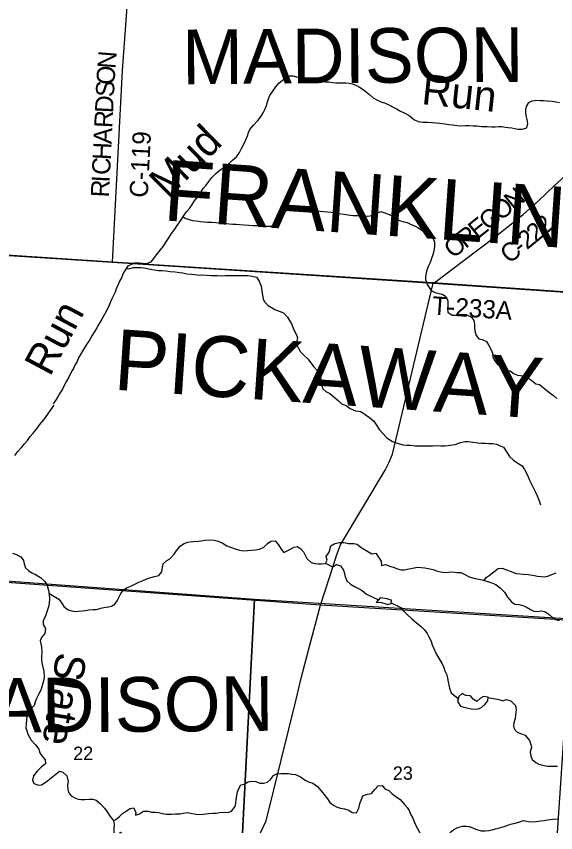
# Model space of a CAD drawing. Extents: x 114843 to 284848, y 317643 to 566895.
# Drawn here: x 240725 to 249598, y 317643 to 331087 of the extents above; entities that cross this region are included whole.
import ezdxf

# ---------------------------------------------------------------- set-up
doc = ezdxf.new("R2010")
doc.units = 0
for name, color, linetype in [('GM_X_County', 7, 'Continuous'), ('GM_X_County_Road', 7, 'Continuous'), ('GM_X_County_Road_Text', 7, 'Continuous'), ('GM_X_County_Text', 7, 'Continuous'), ('GM_X_Minor_Lake', 7, 'Continuous'), ('GM_X_Minor_River', 7, 'Continuous'), ('GM_X_Minor_River_Text', 7, 'Continuous'), ('GM_X_Section', 7, 'Continuous'), ('GM_X_Section_Text', 7, 'Continuous'), ('GM_X_Township', 7, 'Continuous'), ('GM_X_Township_Road', 7, 'Continuous'), ('GM_X_Township_Road_Text', 7, 'Continuous'), ('GM_X_Township_Text', 7, 'Continuous')]:
    doc.layers.add(name, color=color, linetype=linetype)

msp = doc.modelspace()

# ---------------------------------------------------------------- linework, layer by layer
at = {"layer": 'GM_X_County'}
for points in [[(256093, 333696), (255814, 329636), (255762, 328822), (255618, 326883), (255575, 326129), (250997, 326464), (247583, 326697), (242307, 327039), (239655, 327214), (237015, 327375), (235162, 327503), (234342, 327551), (226718, 328004)], [(226718, 328004), (234342, 327551), (235162, 327503), (237015, 327375), (239655, 327214), (242307, 327039), (247583, 326697), (250997, 326464), (255575, 326129), (255217, 320838), (255033, 318174), (254997, 317643)]]:
    msp.add_lwpolyline(points, dxfattribs=at)
at = {"layer": 'GM_X_County_Road'}
msp.add_line((242308, 327036), (247584, 326695), dxfattribs=at)
for points in [[(242308, 327036), (242471, 330193), (242573, 331623), (242715, 333489)], [(247584, 326695), (247638, 326724), (248073, 327052), (248608, 327461), (249062, 327824), (249315, 328047), (249579, 328303), (249934, 328627), (250418, 329010), (250414, 329113), (250426, 329371), (250481, 330134), (250500, 330420)], [(237016, 327373), (239656, 327212), (239661, 327211), (242308, 327036)], [(244744, 317643), (244836, 317836), (245331, 319839), (245413, 320188), (245534, 320650), (245663, 321145), (245728, 321388), (245946, 322063), (245997, 322223), (246060, 322382), (246793, 323614), (246855, 323734), (246912, 323877), (247584, 326695)]]:
    msp.add_lwpolyline(points, dxfattribs=at)
at = {"layer": 'GM_X_Minor_Lake'}
for points in [[(246824, 321492), (246713, 321513), (246645, 321434)], [(246645, 321434), (246713, 321437), (246771, 321421), (246839, 321399), (246891, 321419), (246899, 321471), (246837, 321489), (246824, 321492)], [(248005, 319888), (247984, 319806), (248032, 319724), (248086, 319712), (248156, 319696), (248210, 319680), (248274, 319676), (248330, 319684), (248385, 319709), (248439, 319757), (248481, 319817), (248485, 319873), (248413, 319887), (248363, 319859), (248299, 319801), (248243, 319840), (248197, 319896), (248123, 319902), (248108, 319910)], [(248108, 319910), (248059, 319934), (248005, 319888)]]:
    msp.add_lwpolyline(points, dxfattribs=at)
at = {"layer": 'GM_X_Minor_River'}
for points in [[(242556, 326975), (242671, 327029), (242749, 327028), (242803, 327022), (242869, 327014), (242941, 327045), (242986, 327099), (243048, 327179), (243096, 327242), (243145, 327302), (243189, 327372), (243232, 327439), (243278, 327511), (243330, 327581), (243373, 327644), (243415, 327700), (243447, 327752), (243483, 327804), (243532, 327871), (243574, 327923), (243614, 327977), (243653, 328040), (243711, 328116), (243749, 328168), (243800, 328251), (243848, 328307), (243890, 328369), (243943, 328434), (244009, 328500), (244079, 328556), (244158, 328615), (244230, 328671), (244282, 328716), (244347, 328774), (244397, 328846), (244431, 328911), (244466, 328981), (244500, 329053), (244528, 329119), (244547, 329172), (244569, 329222), (244629, 329296), (244698, 329369), (244754, 329445), (244786, 329497), (244811, 329552), (244839, 329618), (244855, 329680), (244872, 329730), (244896, 329784), (244942, 329853), (244993, 329927), (245049, 329991), (245099, 330032), (245172, 330084), (245222, 330106), (245276, 330105), (245332, 330091), (245386, 330075), (245448, 330054), (245500, 330034), (245560, 330022), (245616, 330014), (245680, 330015), (245746, 330011), (245806, 330007), (245866, 330006), (245928, 329998), (245982, 329994), (246036, 329993), (246092, 329991), (246144, 329989), (246198, 329986), (246258, 329974), (246320, 329948), (246372, 329922), (246430, 329881), (246482, 329843), (246535, 329797), (246593, 329747), (246657, 329712), (246721, 329680), (246781, 329662), (246851, 329629), (246923, 329593), (246979, 329563), (247045, 329525), (247107, 329498), (247186, 329454), (247262, 329390), (247334, 329355), (247412, 329343), (247490, 329344), (247572, 329338), (247634, 329334), (247692, 329327), (247772, 329317), (247840, 329307), (247898, 329302), (247976, 329290)], [(247976, 329290), (248040, 329285), (248113, 329287), (248169, 329287), (248239, 329284), (248303, 329282), (248379, 329274), (248473, 329271), (248549, 329267), (248605, 329268), (248661, 329272), (248713, 329270), (248767, 329264), (248819, 329257), (248875, 329249), (248927, 329239), (248983, 329230), (249049, 329226), (249121, 329248), (249140, 329322), (249130, 329389), (249114, 329452), (249108, 329503), (249107, 329553), (249117, 329603), (249159, 329665), (249209, 329695), (249284, 329704), (249344, 329702), (249400, 329698), (249458, 329693), (249538, 329691), (249662, 329668)], [(243471, 327787), (243511, 327758), (243569, 327739), (243621, 327727), (243685, 327717), (243755, 327708), (243815, 327700), (243871, 327698), (243943, 327695), (244009, 327689), (244069, 327685), (244147, 327680), (244224, 327672), (244286, 327666), (244342, 327663), (244398, 327659), (244474, 327655), (244550, 327648), (244614, 327644), (244682, 327641), (244738, 327637), (244794, 327631), (244860, 327629), (244912, 327632), (244982, 327660), (245038, 327723), (245079, 327781), (245121, 327833), (245167, 327889), (245228, 327914), (245306, 327922), (245382, 327913), (245438, 327907), (245492, 327899), (245568, 327894), (245666, 327884), (245726, 327878), (245784, 327875), (245844, 327867), (245902, 327861), (245980, 327854), (246038, 327840), (246118, 327826), (246178, 327817), (246264, 327807), (246336, 327804), (246388, 327806), (246440, 327802), (246510, 327795), (246580, 327805), (246653, 327847), (246721, 327874), (246773, 327858), (246859, 327822), (246913, 327795), (246968, 327757), (247026, 327727), (247100, 327702), (247154, 327690), (247212, 327666), (247278, 327638), (247330, 327611), (247400, 327561), (247452, 327511), (247518, 327482), (247585, 327430), (247605, 327370), (247605, 327294), (247596, 327218), (247578, 327158), (247554, 327099), (247532, 327031), (247505, 326979), (247479, 326909), (247469, 326859), (247454, 326802), (247458, 326752), (247486, 326671)], [(242558, 326976), (242518, 326909), (242484, 326855), (242459, 326791), (242421, 326723), (242399, 326670), (242369, 326598), (242349, 326546), (242326, 326488), (242296, 326436), (242276, 326384), (242252, 326329), (242200, 326225), (242161, 326151), (242131, 326099), (242083, 326017), (242049, 325956), (242017, 325900), (241966, 325824), (241930, 325756), (241888, 325699), (241850, 325637), (241817, 325585), (241779, 325519), (241747, 325465), (241727, 325401), (241689, 325344), (241664, 325288), (241634, 325236), (241586, 325146), (241550, 325080), (241514, 325009), (241485, 324945), (241443, 324883), (241407, 324819), (241371, 324761), (241333, 324704)], [(242533, 326932), (242574, 326929), (242646, 326950), (242700, 326952), (242780, 326950), (242854, 326938), (242932, 326924), (242994, 326912), (243062, 326903), (243119, 326899), (243183, 326893), (243253, 326883), (243339, 326879), (243409, 326870), (243463, 326862), (243529, 326848), (243607, 326838), (243667, 326834), (243725, 326824), (243795, 326829), (243857, 326825), (243927, 326821), (243979, 326819), (244036, 326819), (244096, 326815), (244162, 326818), (244242, 326818), (244306, 326820), (244376, 326818), (244430, 326820), (244482, 326820), (244534, 326817), (244606, 326805), (244678, 326791), (244722, 326725), (244754, 326645), (244766, 326565), (244774, 326495), (244787, 326435), (244807, 326383), (244867, 326325), (244979, 326257), (245051, 326229), (245119, 326203), (245185, 326135), (245219, 326077), (245255, 326009), (245287, 325937), (245319, 325873), (245349, 325795), (245332, 325723), (245340, 325673), (245366, 325621), (245402, 325559), (245452, 325509), (245524, 325443), (245564, 325387), (245618, 325317), (245678, 325251), (245707, 325197), (245737, 325115), (245751, 325061), (245751, 325003), (245765, 324951), (245819, 324907), (245883, 324873), (245951, 324821), (246019, 324762), (246077, 324706), (246151, 324678), (246219, 324626), (246305, 324592), (246393, 324580), (246463, 324532), (246537, 324481), (246605, 324421), (246648, 324353), (246698, 324277), (246764, 324205), (246820, 324147), (246916, 324087), (246994, 324055), (247084, 324029), (247148, 324022), (247204, 324022), (247284, 324016), (247338, 324014), (247395, 324012), (247467, 324012), (247521, 324015), (247579, 324015), (247647, 324017), (247709, 324013), (247771, 324015), (247829, 324021), (247893, 324028), (247945, 324034), (248030, 324068), (248108, 324084), (248160, 324085), (248236, 324075)], [(247486, 326671), (247547, 326571), (247615, 326541), (247681, 326523), (247736, 326513), (247793, 326471), (247825, 326403), (247825, 326325), (247817, 326273), (247825, 326215), (247895, 326167), (247949, 326167), (248003, 326175), (248057, 326177), (248123, 326176), (248213, 326134), (248253, 326078), (248265, 326018), (248265, 325958), (248267, 325908), (248290, 325830), (248336, 325776), (248390, 325764), (248460, 325732), (248500, 325668), (248538, 325596), (248558, 325538), (248566, 325480), (248594, 325418), (248636, 325364), (248718, 325296), (248774, 325264), (248848, 325246), (248914, 325202), (248968, 325178), (249020, 325171), (249072, 325169), (249142, 325133), (249206, 325091), (249272, 325035), (249334, 325021), (249422, 324953), (249508, 324879), (249560, 324844), (249617, 324794)], [(240701, 323853), (240748, 323919), (240812, 323984), (240860, 324044), (240909, 324100), (240953, 324167), (241003, 324221), (241056, 324289), (241104, 324359), (241175, 324444), (241347, 324683)], [(248236, 324075), (248316, 324065), (248378, 324059), (248442, 324055), (248498, 324053), (248564, 324052), (248626, 324042), (248686, 324016), (248738, 323992), (248790, 323916), (248840, 323840), (248902, 323776), (248978, 323728), (249046, 323684), (249086, 323622), (249122, 323554), (249145, 323504), (249169, 323450), (249219, 323352), (249265, 323250), (249291, 323188), (249321, 323124), (249349, 323042)], [(241260, 321589), (241422, 321490), (241462, 321440), (241508, 321368), (241578, 321314), (241638, 321294), (241692, 321288), (241744, 321290), (241808, 321295), (241862, 321303), (241918, 321313), (241987, 321317), (242041, 321317), (242113, 321338), (242167, 321354), (242239, 321360), (242291, 321376), (242345, 321408), (242383, 321460), (242412, 321515), (242440, 321571), (242484, 321639), (242536, 321677), (242596, 321699), (242666, 321730), (242739, 321770), (242823, 321800), (242899, 321832), (242999, 321863), (243071, 321879), (243118, 321939), (243130, 322013), (243138, 322073), (243200, 322124), (243250, 322152), (243319, 322228), (243365, 322294), (243423, 322369), (243485, 322403), (243549, 322425), (243630, 322437), (243714, 322446), (243766, 322450), (243828, 322462), (243896, 322468), (243978, 322458), (244048, 322443), (244110, 322415), (244188, 322367), (244262, 322337), (244324, 322315), (244398, 322297), (244458, 322287), (244530, 322290), (244594, 322294), (244659, 322302), (244727, 322314), (244795, 322343), (244859, 322407), (244911, 322443), (244983, 322449), (245037, 322381), (245083, 322311), (245127, 322255), (245179, 322283), (245293, 322346), (245344, 322358), (245408, 322320), (245448, 322268), (245505, 322156), (245575, 322094), (245635, 322076), (245691, 322069), (245743, 322071), (245809, 322077), (245840, 322131), (245824, 322191), (245870, 322261), (245900, 322366), (245965, 322408), (246043, 322424), (246115, 322422), (246189, 322406), (246279, 322407), (246331, 322395), (246397, 322341), (246451, 322309), (246517, 322267), (246571, 322233), (246641, 322246), (246681, 322180), (246727, 322112), (246735, 322043), (246799, 322058), (246871, 322032), (246943, 322012), (246995, 321986), (247055, 321972), (247107, 321972), (247181, 321987), (247245, 321999)], [(240662, 322246), (240730, 322222), (240800, 322186), (240841, 322124), (240851, 322072), (240875, 322002), (240927, 321958), (240981, 321924), (241039, 321894), (241124, 321843), (241192, 321781), (241232, 321711), (241252, 321633), (241263, 321573), (241273, 321498), (241263, 321418), (241254, 321364), (241232, 321298), (241204, 321212), (241167, 321133), (241167, 321071), (241203, 321003), (241192, 320923), (241140, 320855), (241118, 320803), (241127, 320752), (241137, 320700), (241147, 320622), (241140, 320534), (241140, 320478), (241148, 320418), (241158, 320368), (241177, 320296), (241183, 320212), (241179, 320159), (241162, 320107), (241142, 320043), (241126, 319991), (241093, 319927), (241061, 319864), (241035, 319796), (241018, 319738), (240966, 319680), (240922, 319619), (240899, 319565), (240893, 319497), (240887, 319437), (240883, 319371), (240896, 319321), (240914, 319267), (240940, 319215), (240970, 319165), (241039, 319089), (241093, 319017), (241109, 318959), (241145, 318907), (241197, 318843), (241204, 318777), (241134, 318722), (241067, 318656), (241009, 318582), (240993, 318508), (241014, 318451), (241088, 318424), (241139, 318430), (241213, 318478), (241433, 318656)], [(245811, 322080), (245925, 322019), (245990, 322057), (246056, 322036), (246110, 321966), (246123, 321910), (246135, 321856), (246163, 321793), (246221, 321736), (246291, 321696), (246343, 321672), (246413, 321630), (246485, 321570), (246683, 321478)], [(247245, 321999), (247325, 322015), (247387, 322009), (247445, 322003), (247527, 321990), (247582, 321978), (247636, 321956), (247702, 321938), (247778, 321930), (247836, 321932), (247898, 321937), (247970, 321929), (248036, 321927), (248114, 321889), (248176, 321857), (248272, 321829), (248336, 321818), (248388, 321806), (248446, 321792), (248500, 321772), (248558, 321754), (248616, 321728), (248686, 321674), (248754, 321602), (248808, 321520), (248874, 321445), (248926, 321409), (249000, 321399), (249074, 321381), (249130, 321349), (249184, 321317), (249240, 321291), (249300, 321283), (249358, 321298), (249422, 321288), (249490, 321238), (249542, 321190), (249596, 321154), (249656, 321138)], [(248420, 321798), (248454, 321846), (248506, 321876), (248579, 321938), (248651, 321995), (248717, 321997), (248787, 321973), (248849, 321949), (248949, 321911), (249067, 321900), (249145, 321896), (249223, 321882), (249299, 321868), (249361, 321861), (249414, 321859), (249468, 321867), (249546, 321903), (249606, 321921)], [(246892, 321429), (247053, 321353), (247093, 321295), (247155, 321235), (247231, 321166), (247303, 321106), (247389, 321032), (247441, 320986), (247483, 320926), (247509, 320866), (247548, 320796), (247568, 320734), (247592, 320674), (247630, 320590), (247680, 320508), (247724, 320434), (247758, 320364), (247777, 320306), (247805, 320242), (247817, 320190), (247831, 320126), (247843, 320074), (247853, 320024), (247879, 319944), (247996, 319854)], [(248484, 319868), (248669, 319838), (248721, 319816), (248789, 319838), (248862, 319814), (248935, 319736), (248949, 319668), (248939, 319576), (248929, 319526), (248907, 319454), (248905, 319404), (248914, 319354), (248962, 319300), (249034, 319272), (249096, 319248), (249166, 319160), (249192, 319096), (249198, 319046), (249176, 318974), (249192, 318904), (249213, 318850), (249271, 318798), (249323, 318772), (249407, 318748), (249461, 318736), (249534, 318736), (249626, 318739)], [(241433, 318656), (241489, 318640), (241553, 318580), (241577, 318488), (241568, 318424), (241574, 318356), (241590, 318300), (241628, 318248), (241686, 318216), (241742, 318196), (241794, 318190), (241850, 318192), (241926, 318196), (241984, 318195), (242038, 318179), (242112, 318117), (242178, 318045), (242220, 317985), (242268, 317911), (242322, 317843), (242334, 317777), (242330, 317705), (242331, 317643)], [(242323, 317838), (242364, 317859), (242420, 317911), (242474, 317958), (242523, 317992), (242595, 318040), (242655, 318054), (242691, 317980), (242683, 317930), (242751, 317954), (242819, 317999), (242893, 317995), (242951, 317983), (243007, 317979), (243065, 317973), (243129, 317961), (243195, 317950), (243281, 317948), (243346, 317956), (243418, 317954), (243470, 317966), (243536, 317973), (243588, 317963), (243648, 317951), (243716, 317941), (243798, 317947), (243886, 317958), (243958, 317962), (244010, 317966), (244065, 317976), (244141, 317982), (244201, 317974), (244265, 317999), (244323, 318073), (244337, 318129), (244343, 318183), (244350, 318257), (244366, 318317), (244384, 318370), (244420, 318430), (244474, 318440), (244540, 318478), (244593, 318490), (244665, 318484), (244733, 318461), (244789, 318461), (244855, 318475), (244909, 318517), (244953, 318585), (245007, 318612), (245078, 318618), (245144, 318616), (245200, 318616), (245258, 318608), (245320, 318604), (245400, 318565), (245478, 318509), (245534, 318481), (245602, 318457), (245682, 318405), (245736, 318337), (245786, 318277), (245843, 318201), (245881, 318141), (245943, 318095), (246003, 318064), (246057, 318048), (246125, 318036), (246197, 318014), (246249, 317974), (246321, 317972), (246358, 318049), (246374, 318123), (246398, 318177), (246424, 318249), (246500, 318275), (246569, 318289), (246621, 318352), (246675, 318412), (246745, 318422), (246789, 318366), (246851, 318340), (246909, 318284), (246969, 318239), (247039, 318189), (247109, 318109), (247155, 318059), (247185, 318007), (247211, 317949), (247248, 317881), (247276, 317813), (247304, 317751), (247330, 317699), (247360, 317649), (247364, 317643)], [(247864, 317643), (247869, 317654), (247921, 317698), (247991, 317731), (248063, 317751), (248125, 317753), (248177, 317743), (248301, 317695), (248371, 317676), (248437, 317672), (248499, 317678), (248554, 317690), (248610, 317704), (248676, 317723), (248748, 317743), (248802, 317761), (248856, 317781), (248934, 317799), (248990, 317816), (249067, 317844), (249149, 317826), (249221, 317824), (249279, 317830), (249349, 317839), (249407, 317845), (249465, 317855), (249549, 317865), (249629, 317873)], [(242422, 317643), (242440, 317651), (242457, 317643)]]:
    msp.add_lwpolyline(points, dxfattribs=at)
at = {"layer": 'GM_X_Section'}
for points in [[(239073, 317643), (239297, 321883), (244644, 321491), (244444, 317643)], [(244444, 317643), (244644, 321491), (249860, 321163), (249622, 317643)]]:
    msp.add_lwpolyline(points, dxfattribs=at)
at = {"layer": 'GM_X_Township'}
for points in [[(256093, 333696), (255814, 329636), (255762, 328822), (255618, 326883), (255575, 326129), (250997, 326464), (247583, 326697), (242307, 327039), (239655, 327214), (237015, 327375), (235162, 327503), (234342, 327551), (226718, 328004)], [(223195, 317643), (223490, 322917), (223643, 325525), (223790, 328228), (226718, 328004), (234342, 327551), (235162, 327503), (237015, 327375), (239655, 327214), (242307, 327039), (247583, 326697), (250997, 326464), (255575, 326129), (255217, 320838), (255033, 318174), (254997, 317643)]]:
    msp.add_lwpolyline(points, dxfattribs=at)
at = {"layer": 'GM_X_Township_Road'}
for p, q in [((242308, 327036), (247584, 326695)), ((247584, 326695), (250998, 326461))]:
    msp.add_line(p, q, dxfattribs=at)
for points in [[(237016, 327373), (239656, 327212), (239661, 327211), (242308, 327036)], [(251475, 321041), (245728, 321388), (239269, 321854), (232051, 322320)]]:
    msp.add_lwpolyline(points, dxfattribs=at)

# ---------------------------------------------------------------- texts
at = {"layer": 'GM_X_County_Road_Text'}
for s, rotation, p in [('N', 85.5085, (242355, 330216)), ('O', 86.6994, (242339, 329954)), ('S', 87.1622, (242329, 329753)), ('D', 87.1742, (242316, 329489)), ('R', 87.1728, (242304, 329243)), ('A', 87.1732, (242291, 328979)), ('C-119', 87.1118, (242886, 328095)), ('H', 87.1738, (242278, 328716)), ('C', 87.1764, (242266, 328469)), ('I', 87.1729, (242260, 328346)), ('R', 87.1728, (242248, 328100)), ('N', 39.859, (248905, 327879)), ('O', 38.4802, (248692, 327710)), ('G', 38.4002, (248485, 327546)), ('E', 38.3991, (248309, 327406)), ('2', 40.8421, (249419, 327475)), ('R', 38.3964, (248116, 327253)), ('2', 39.3975, (249270, 327352)), ('2', 39.0003, (249125, 327235)), ('O', 38.398, (247909, 327089)), ('C', 38.8103, (248836, 327002)), ('-', 38.8412, (249028, 327157))]:
    msp.add_text(s, height=300, rotation=rotation, dxfattribs=at).set_placement(p)
at = {"layer": 'GM_X_County_Text'}
for s, rotation, p in [('FRANKLIN COUNTY', 356.0636, (243129, 327728)), ('PICKAWAY COUNTY', 356.1007, (242312, 324940))]:
    msp.add_text(s, height=1000.09, rotation=rotation, dxfattribs=at).set_placement(p)
at = {"layer": 'GM_X_Minor_River_Text'}
for s, height, rotation, p in [('Run', 500, 353.8282, (247378, 329643)), ('Mud', 500.1, 44.7679, (243215, 328072)), ('Run', 500.1, 61.936, (241278, 325139)), ('Slate', 500, 260.9336, (241390, 320631))]:
    msp.add_text(s, height=height, rotation=rotation, dxfattribs=at).set_placement(p)
at = {"layer": 'GM_X_Section_Text'}
for s, rotation, p in [('22', 0.4139, (241661, 318838)), ('23', 0.414, (246920, 318513))]:
    msp.add_text(s, height=221, rotation=rotation, dxfattribs=at).set_placement(p)
at = {"layer": 'GM_X_Township_Road_Text'}
msp.add_text('T-233A', height=300, rotation=356.0653, dxfattribs=at).set_placement((247559, 326178))
at = {"layer": 'GM_X_Township_Text'}
for rotation, p in [(0.414, (243454, 329968)), (0.4139, (239340, 319281))]:
    msp.add_text('MADISON', height=900.1, rotation=rotation, dxfattribs=at).set_placement(p)

doc.saveas('drawing.dxf')
